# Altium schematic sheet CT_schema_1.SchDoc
size 719 x 519 mm
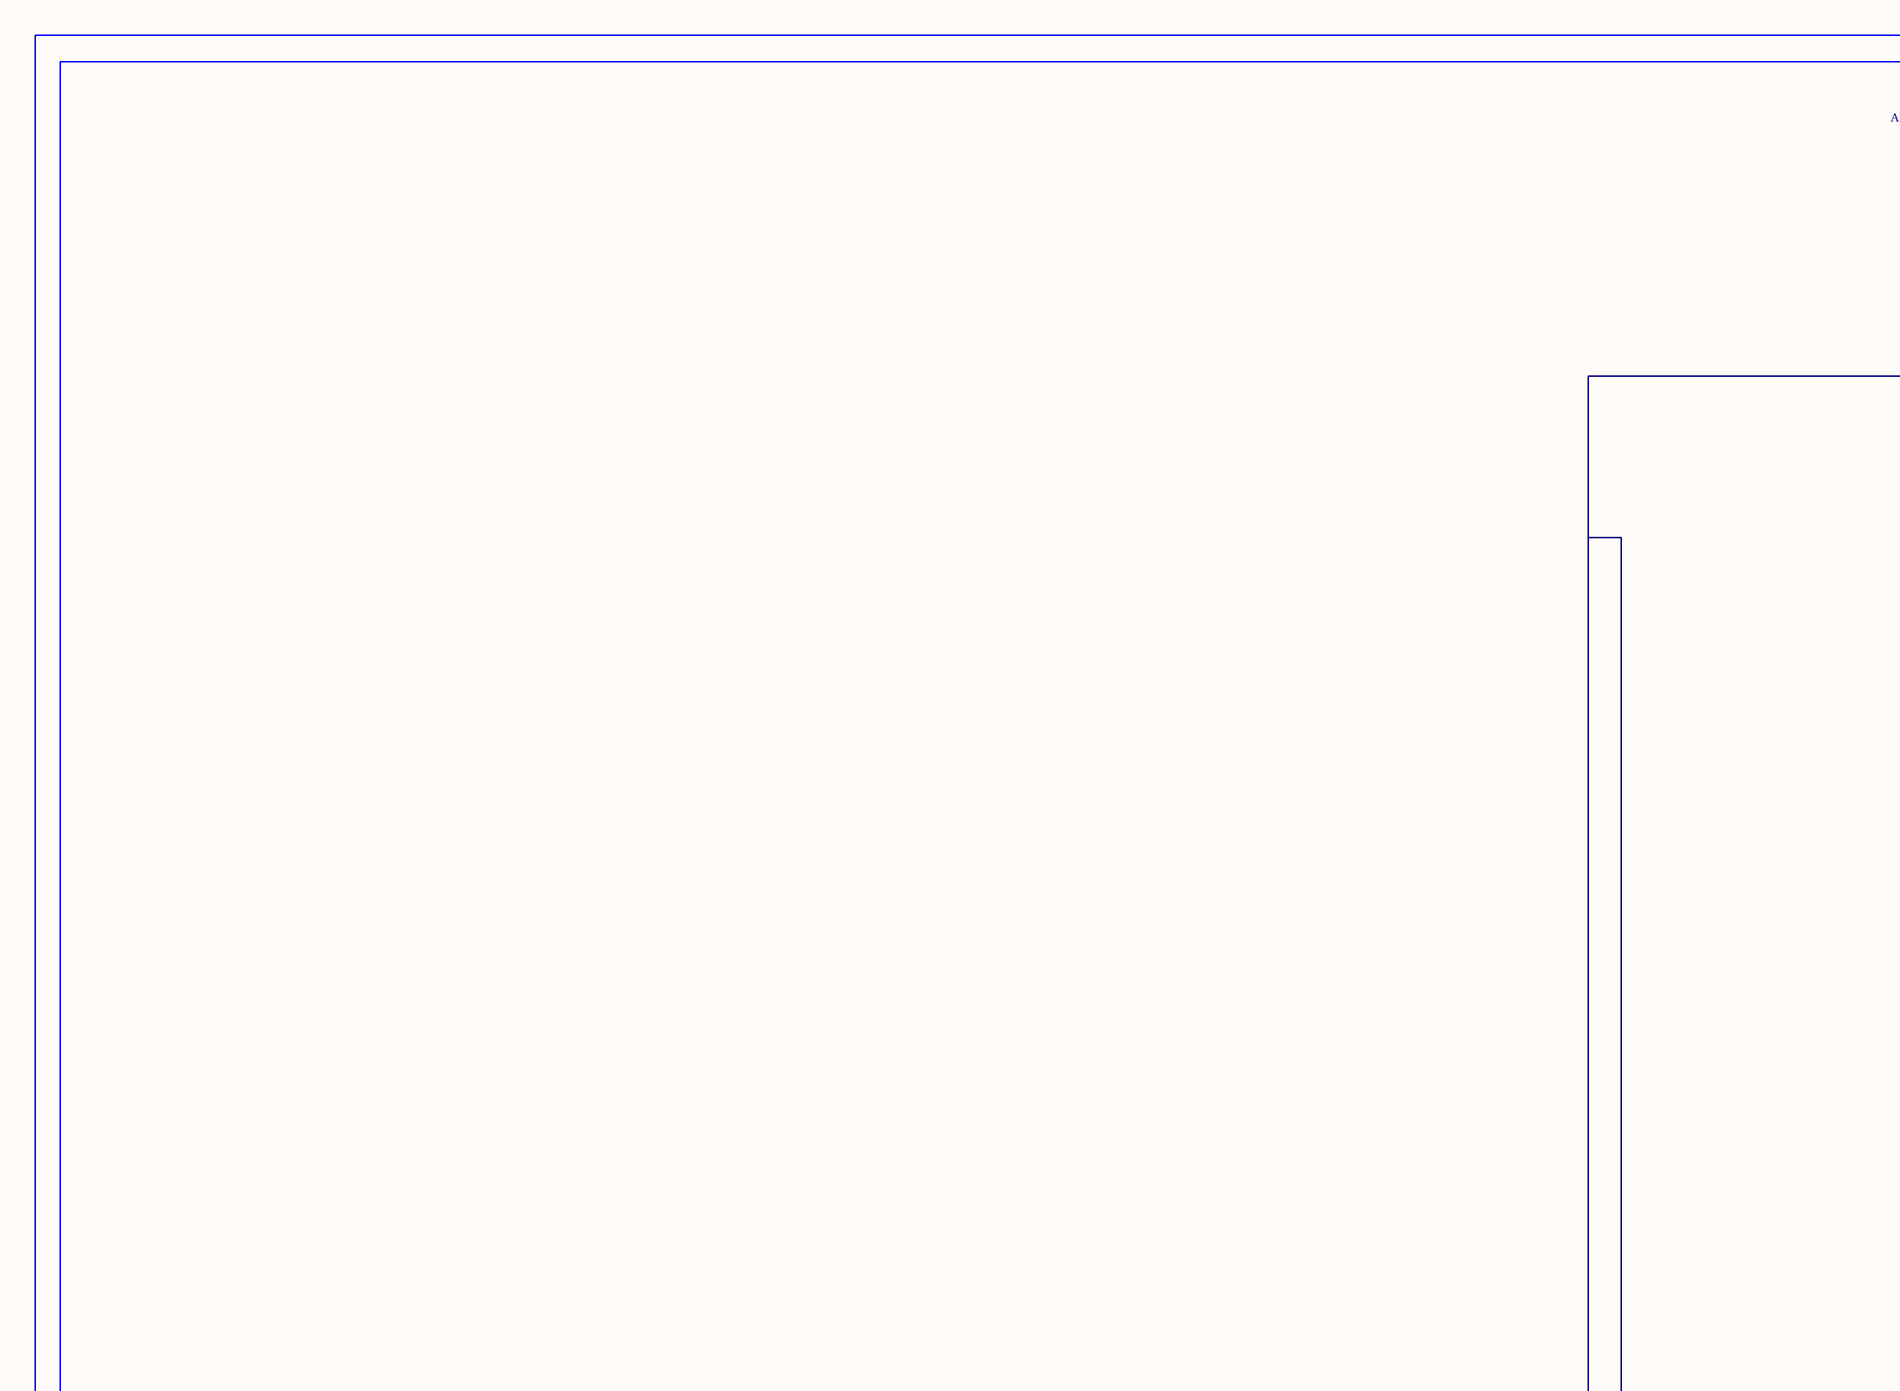
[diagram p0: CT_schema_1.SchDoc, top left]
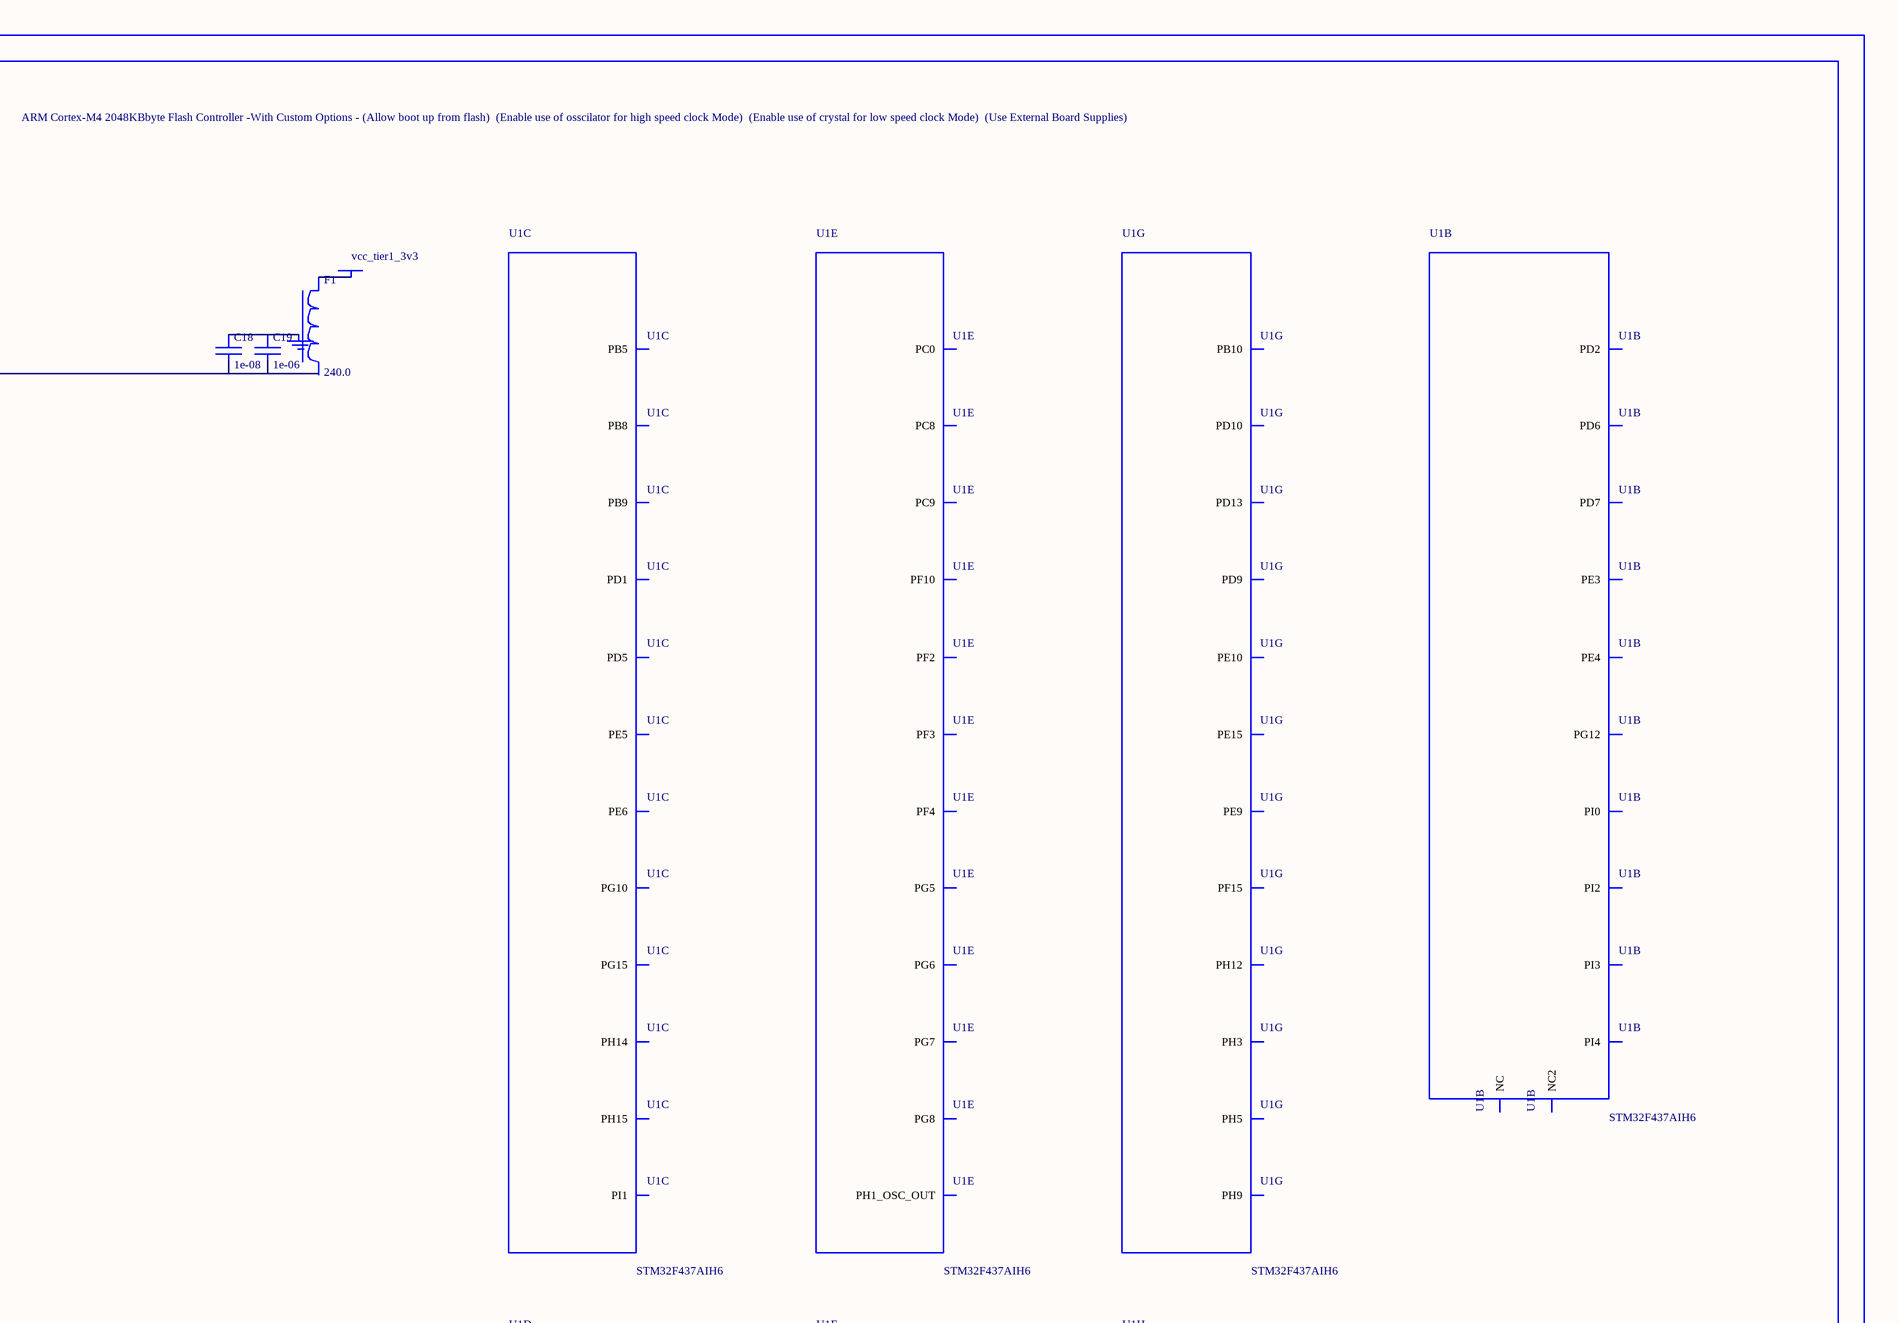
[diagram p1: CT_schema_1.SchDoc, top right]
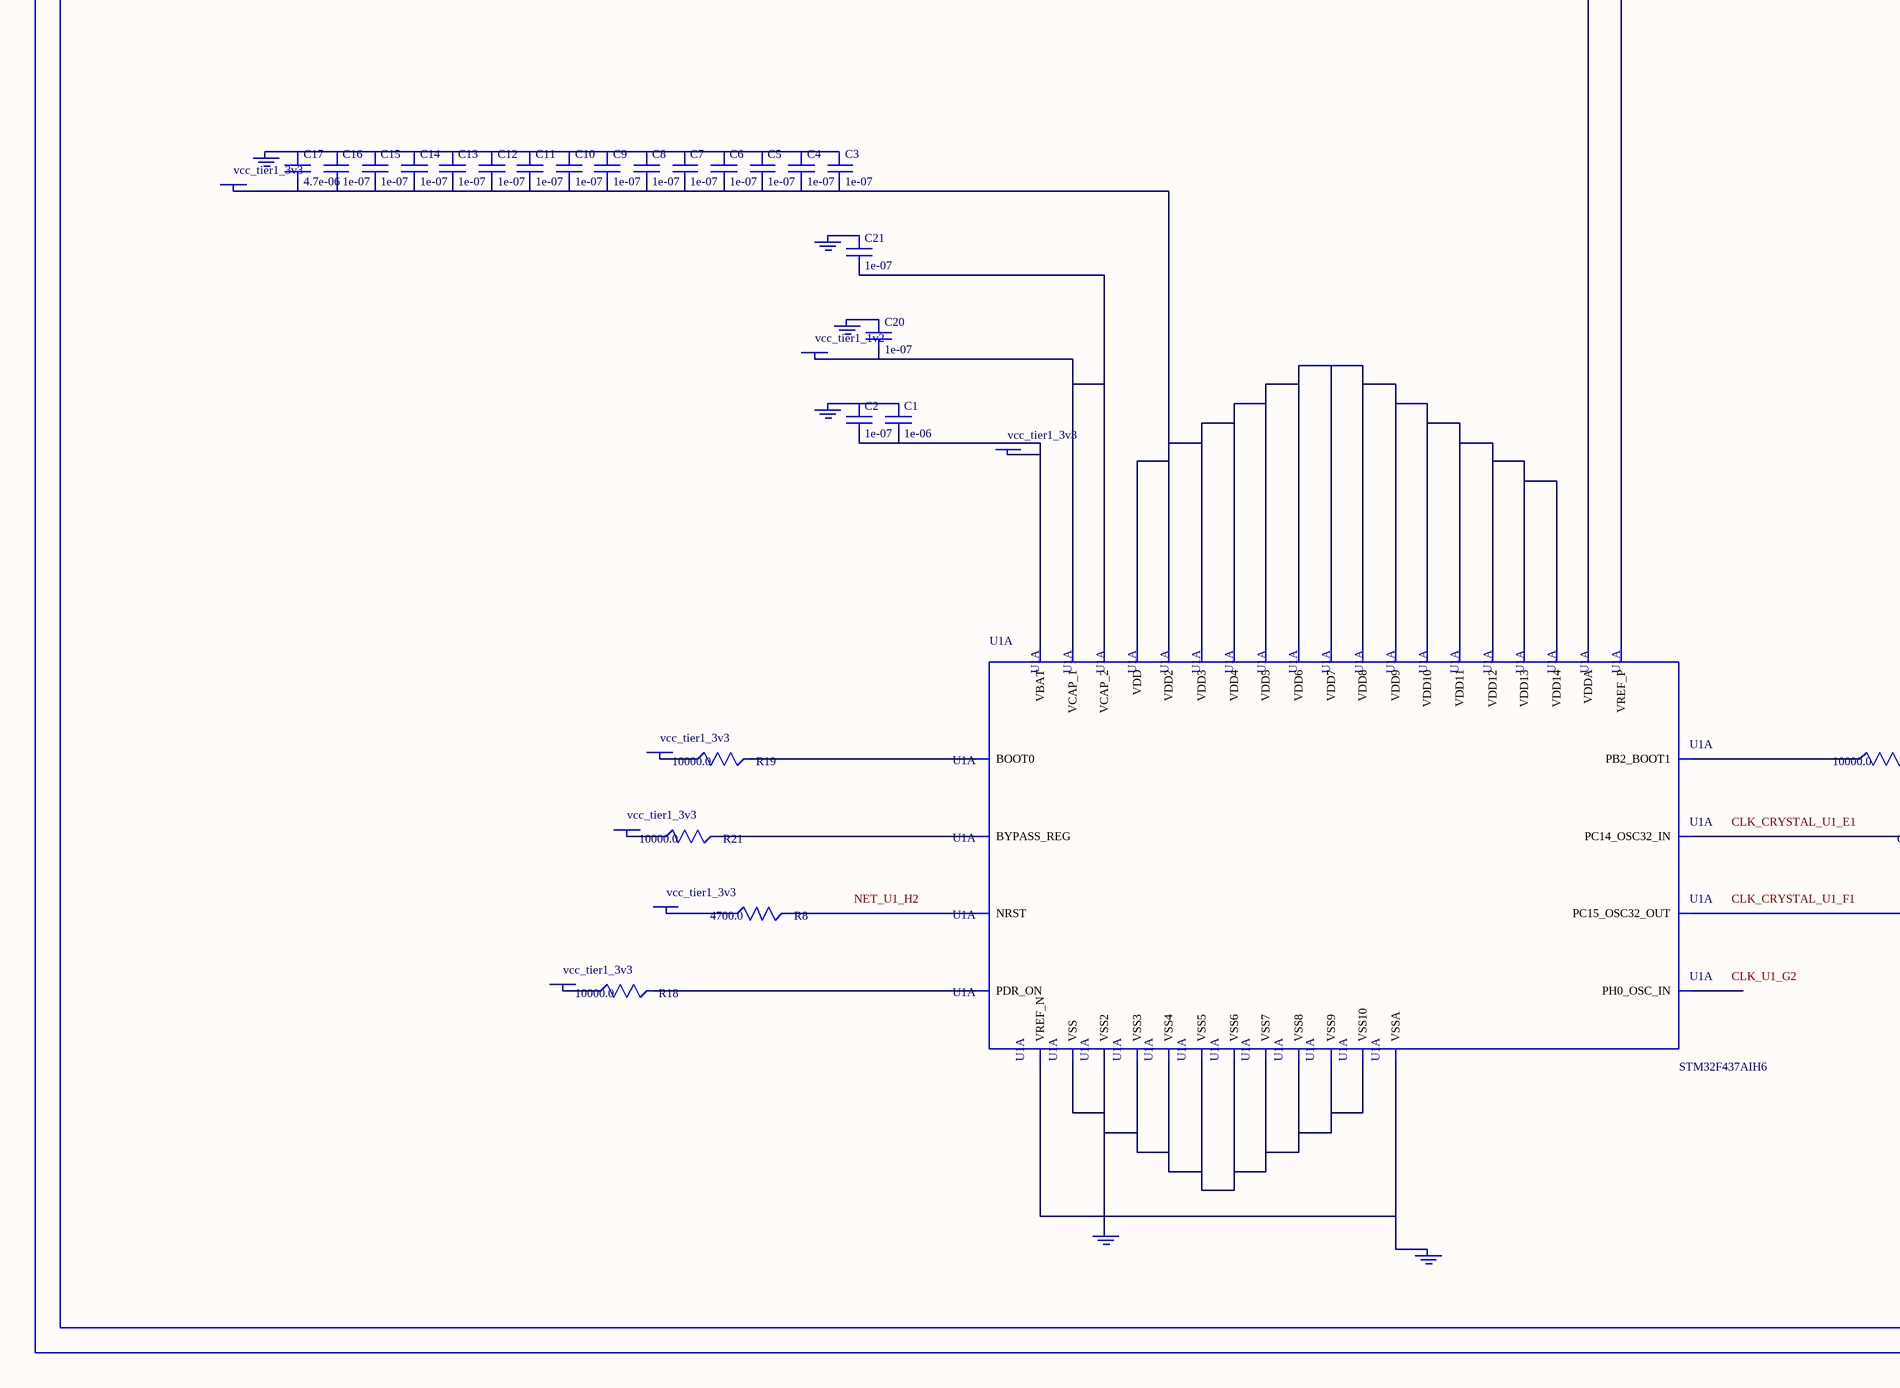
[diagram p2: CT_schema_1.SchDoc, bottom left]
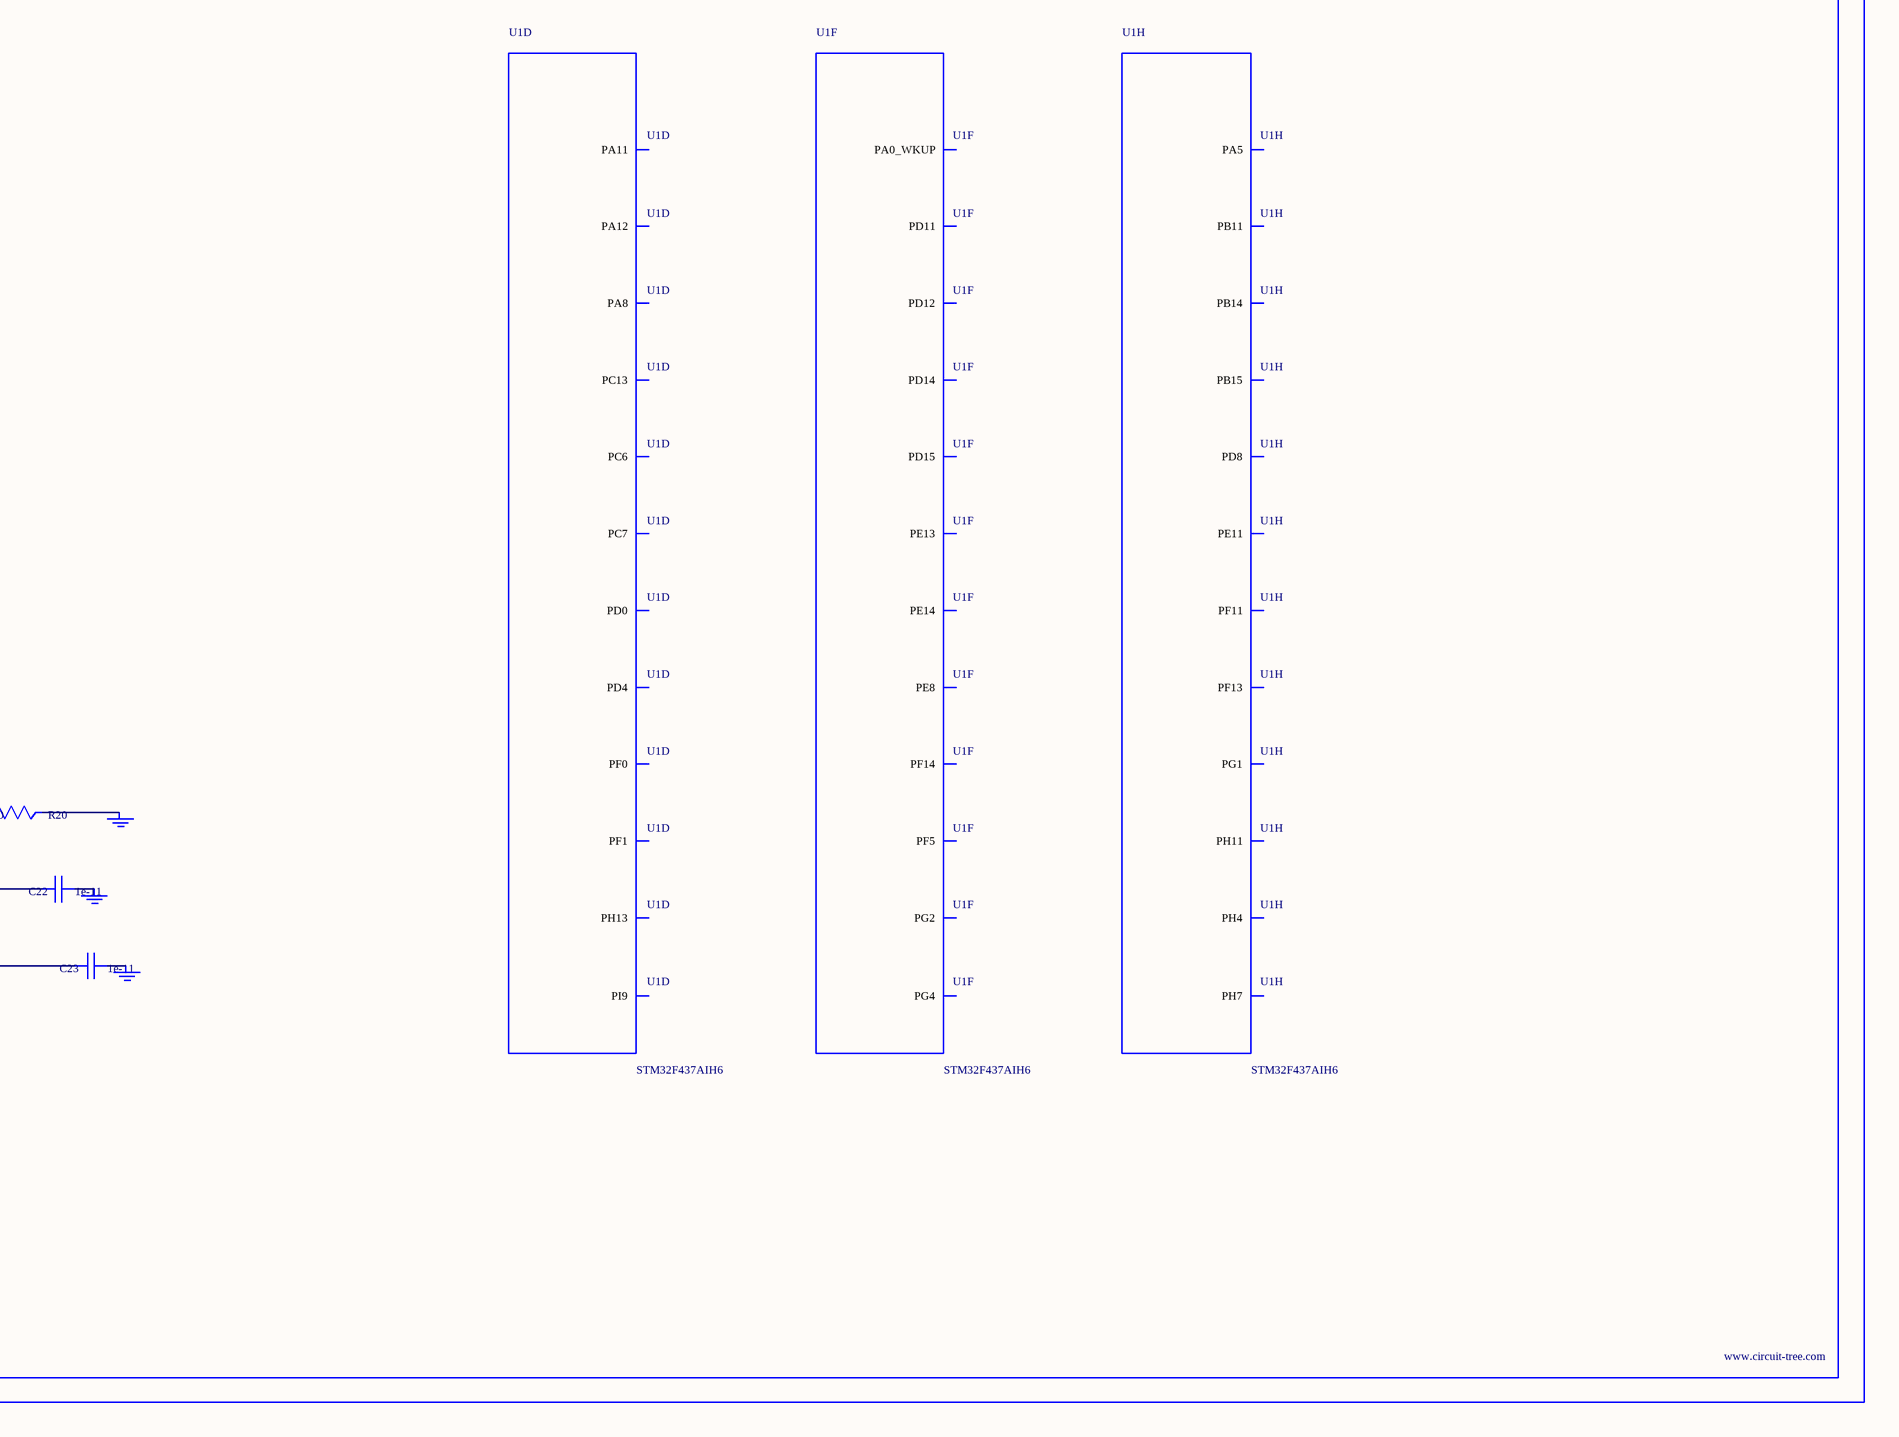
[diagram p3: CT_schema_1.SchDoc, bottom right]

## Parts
BORDER0  (no value)
C1  1e-06  [C0603]
C2  1e-07  [C0603]
C3  1e-07  [C0603]
C4  1e-07  [C0603]
C5  1e-07  [C0603]
C6  1e-07  [C0603]
C7  1e-07  [C0603]
C8  1e-07  [C0603]
C9  1e-07  [C0603]
C10  1e-07  [C0603]
C11  1e-07  [C0603]
C12  1e-07  [C0603]
C13  1e-07  [C0603]
C14  1e-07  [C0603]
C15  1e-07  [C0603]
C16  1e-07  [C0603]
C17  4.7e-06  [C0603]
C18  1e-08  [C0603]
C19  1e-06  [C0603]
C20  1e-07  [C0402]
C21  1e-07  [C0402]
C22  1e-11  [C0402]
C23  1e-11  [C0402]
F1  240.0  [L0603]
GND_INSTANCE_0_0  (no value)
GND_INSTANCE_0_1  (no value)
GND_INSTANCE_0_2  (no value)
GND_INSTANCE_0_3  (no value)
GND_INSTANCE_0_4  (no value)
GND_INSTANCE_0_5  (no value)
GND_INSTANCE_0_6  (no value)
GND_INSTANCE_0_7  (no value)
GND_INSTANCE_0_8  (no value)
GND_INSTANCE_0_9  (no value)
POWER_INSTANCE_0_0  vcc_tier1_3v3
POWER_INSTANCE_0_1  vcc_tier1_3v3
POWER_INSTANCE_0_2  vcc_tier1_3v3
POWER_INSTANCE_0_3  vcc_tier1_3v3
POWER_INSTANCE_0_4  vcc_tier1_3v3
POWER_INSTANCE_0_5  vcc_tier1_3v3
POWER_INSTANCE_0_6  vcc_tier1_1v2
POWER_INSTANCE_0_7  vcc_tier1_3v3
R8  4700.0  [R0603]
R18  10000.0  [R0603]
R19  10000.0  [R0603]
R20  10000.0  [R0603]
R21  10000.0  [R0603]
U1  STM32F437AIH6  [UFBGA169]  (parts A,B,C,D,E,F,G,H of 12)

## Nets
NetC1_1: C1.1 C2.1 GND_INSTANCE_0_0.0(GND)
NetC1_2: C1.2 C2.2 POWER_INSTANCE_0_0.0(PWR) U1.E5(VBAT)
NetC3_1: C3.1 C4.1 C5.1 C6.1 C7.1 C8.1 C9.1 C10.1 C11.1 C12.1 C13.1 C14.1 C15.1 C16.1 C17.1 GND_INSTANCE_0_2.0(GND)
NetC3_2: C3.2 C4.2 C5.2 C6.2 C7.2 C8.2 C9.2 C10.2 C11.2 C12.2 C13.2 C14.2 C15.2 C16.2 C17.2 POWER_INSTANCE_0_2.0(PWR) U1.D3(VDD2) U1.D6(VDD3) U1.D10(VDD) U1.E6(VDD4) U1.F4(VDD5) U1.F7(VDD6) U1.F8(VDD7) U1.G8(VDD9) U1.G10(VDD8) U1.H4(VDD10) U1.H8(VDD11) U1.J11(VDD12) U1.K6(VDD13) U1.L6(VDD14)
NetC18_1: C18.1 C19.1 GND_INSTANCE_0_1.0(GND)
NetC18_2: C18.2 C19.2 U1.J3(VREF_P) U1.J4(VDDA)
NetC20_1: C20.1 GND_INSTANCE_0_4.0(GND)
NetC20_2: C20.2 C21.2 POWER_INSTANCE_0_6.0(PWR) U1.D12(VCAP_2) U1.N9(VCAP_1)
NetC21_1: C21.1 GND_INSTANCE_0_5.0(GND)
NetC22_1: C22.1 GND_INSTANCE_0_6.0(GND)
NetC22_2: C22.2 U1.E1(PC14_OSC32_IN)
NetC23_1: C23.1 GND_INSTANCE_0_7.0(GND)
NetC23_2: C23.2 U1.F1(PC15_OSC32_OUT)
NetF1_1: F1.1 POWER_INSTANCE_0_1.0(PWR)
NetGND_INSTANCE_0_3_0: GND_INSTANCE_0_3.0(GND) R20.2
NetGND_INSTANCE_0_8_0: GND_INSTANCE_0_8.0(GND) U1.J1(VSSA) U1.J2(VREF_N)
NetGND_INSTANCE_0_9_0: GND_INSTANCE_0_9.0(GND) U1.D7(VSS2) U1.D11(VSS) U1.E7(VSS3) U1.F5(VSS4) U1.F6(VSS5) U1.G7(VSS6) U1.G9(VSS7) U1.J6(VSS9) U1.J7(VSS10) U1.J10(VSS8)
NetPOWER_INSTANCE_0_3_0: POWER_INSTANCE_0_3.0(PWR) R18.1
NetPOWER_INSTANCE_0_4_0: POWER_INSTANCE_0_4.0(PWR) R19.1
NetPOWER_INSTANCE_0_5_0: POWER_INSTANCE_0_5.0(PWR) R21.1
NetPOWER_INSTANCE_0_7_0: POWER_INSTANCE_0_7.0(PWR) R8.1
NetR8_2: R8.2 U1.H2(NRST)
NetR18_2: R18.2 U1.C3(PDR_ON)
NetR19_2: R19.2 U1.A5(BOOT0)
NetR20_1: R20.1 U1.L5(PB2_BOOT1)
NetR21_2: R21.2 U1.M1(BYPASS_REG)

Not connected (* = marked no-connect by the designer): F1 2; U1 A1(NC) A7(PG12) A8(PD7) A12(PI3) A13(NC2) B3(PI4) B8(PD6) B9(PD2) B12(PI2) B13(PI0) C1(PE3) C2(PE4) C4(PB9) C6(PG15) C7(PG10) C8(PD5) C9(PD1) C11(PI1) C12(PH15) C13(PH14) D1(PE5) D2(PE6) D4(PB8) D5(PB5) D8(PD4) D9(PD0) D13(PH13) E2(PI9) E4(PC13) E10(PA11) E11(PA12) E13(PA8) F2(PF0) F3(PF1) F9(PC6) F10(PC7) F11(PC8) F12(PC9) F13(PG8) G1(PH1_OSC_OUT) G2(PH0_OSC_IN) G3(PF4) G4(PF3) G5(PF2) G6(PC0) G11(PG6) G12(PG7) G13(PG5) H1(PF10) H3(PF5) H9(PE13) H10(PD11) H11(PD14) H12(PG4) H13(PG2) J5(PA0_WKUP) J8(PE8) J9(PE14) J12(PD15) J13(PD12) K7(PF14) K8(PE9) K9(PE15) K10(PH9) K11(PD10) K12(PD13) K13(PD9) L1(PH3) L3(PH5) L7(PF15) L8(PE10) L9(PB10) L11(PH12) L12(PD8) L13(PB15) M2(PH4) M3(PA5) M5(PF11) M6(PF13) M7(PG1) M8(PE11) M9(PB11) M10(PH7) M11(PH11) M13(PB14)

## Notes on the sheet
- Labels drawn without touching a wire or pin: CLK_CRYSTAL_U1_E1, CLK_CRYSTAL_U1_F1, CLK_U1_G2, NET_U1_H2

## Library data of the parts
BORDER0 = BORDER_PAGE0
C1 C19 = C0603C105K3RACTU
C2-C16 = 06035C104K4Z2A
C17 = GRM188R6YA475KE15D
C18 = 06035C103K4Z2A
C20 C21 = C0402C104K3RACTU
C22 C23 = C0402C100K3GACTU
F1 = Z0603C241ASMST
GND_INSTANCE_0_0-GND_INSTANCE_0_9 = GND
POWER_INSTANCE_0_0-POWER_INSTANCE_0_7 = PWR
R8 = RC0603JR-074K7L
R18-R21 = RC0603JR-0710KL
